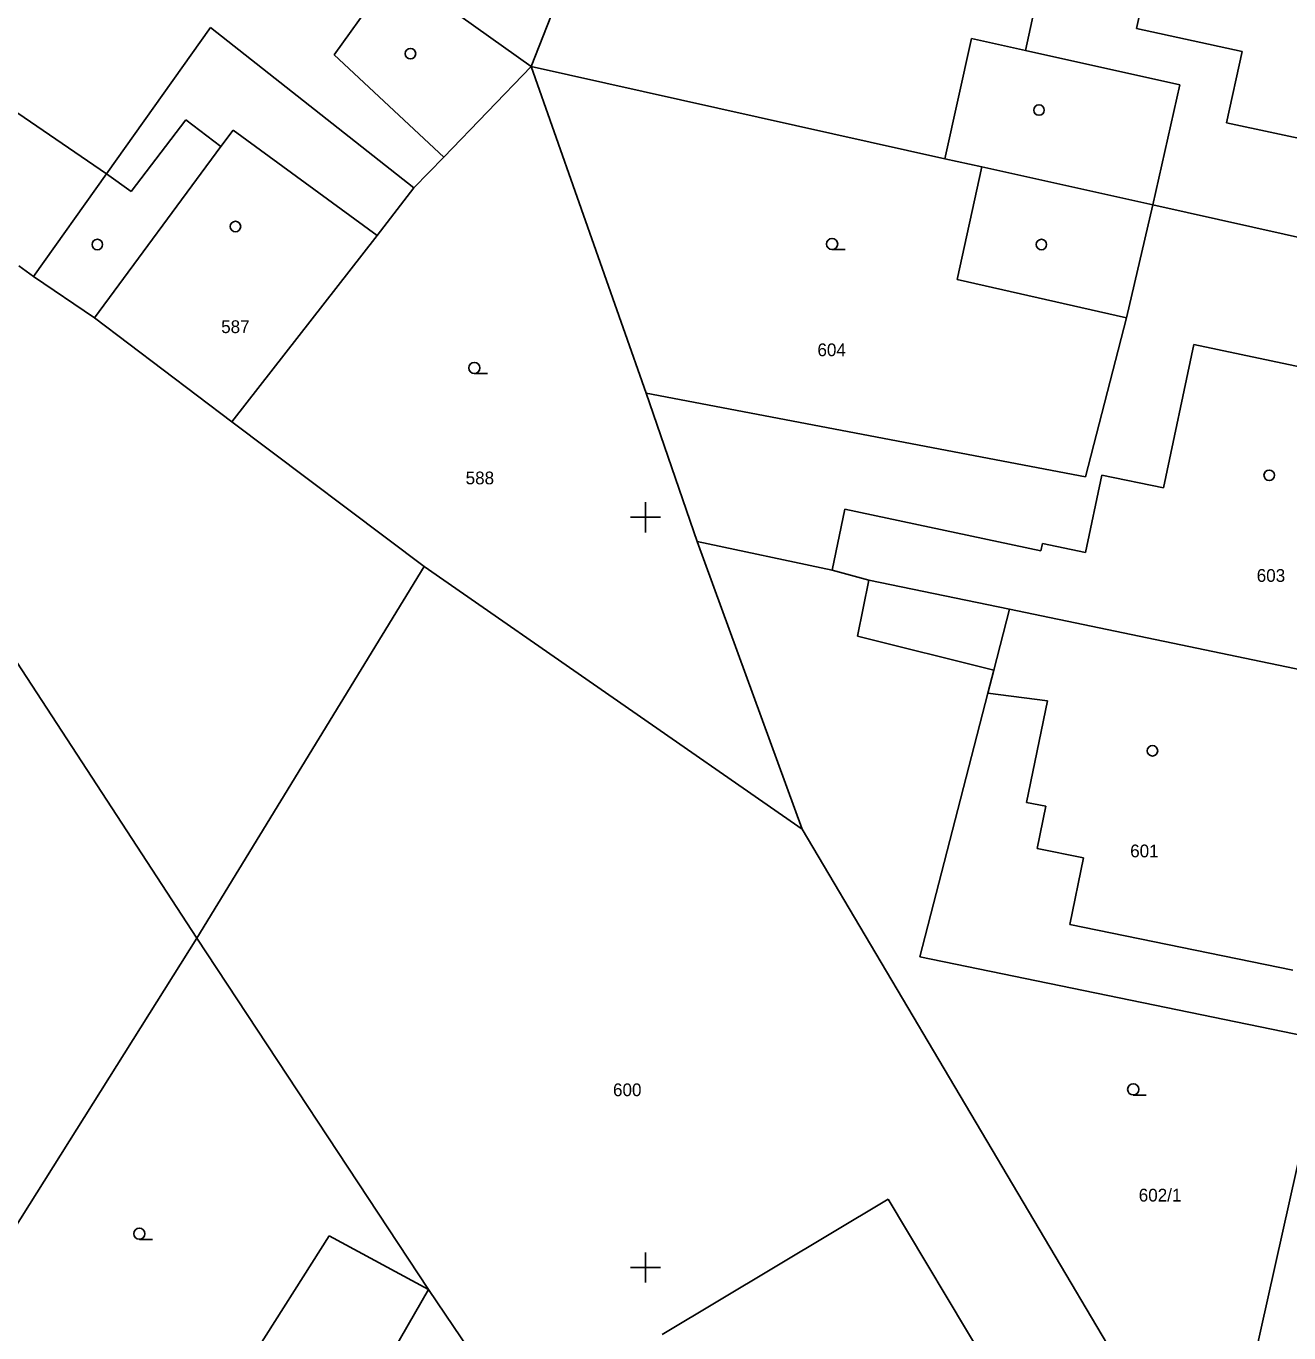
# Model space of a CAD drawing. Extents: x -702257 to -701487, y -1009871 to -1008841.
# Drawn here: x -701770.63 to -701728.56, y -1009477.18 to -1009433.63 of the extents above; entities that cross this region are included whole.
import ezdxf

# ---------------------------------------------------------------- set-up
doc = ezdxf.new("R2010")
doc.units = 0
for name, color, linetype in [('Z_hektometricka_sit', 7, 'Continuous'), ('Z_katastr_cisla_pozemkova', 7, 'Continuous'), ('Z_katastr_cisla_stavebni', 7, 'Continuous'), ('Z_katastr_hranice', 7, 'Continuous'), ('Z_katastr_vnitrni_kresba', 7, 'Continuous'), ('Z_katastr_znacky_budov', 7, 'Continuous'), ('Z_katastr_znacky_kultur', 7, 'Continuous')]:
    doc.layers.add(name, color=color, linetype=linetype)

msp = doc.modelspace()

# ---------------------------------------------------------------- linework, layer by layer
at = {"layer": 'Z_hektometricka_sit'}
for p, q in [((-701750, -1009449.5), (-701750, -1009450.5)), ((-701750, -1009449.5), (-701750, -1009450.5)), ((-701750.5, -1009450), (-701749.5, -1009450)), ((-701750.5, -1009450), (-701749.5, -1009450)), ((-701750, -1009474.5), (-701750, -1009475.5)), ((-701750, -1009474.5), (-701750, -1009475.5)), ((-701750.5, -1009475), (-701749.5, -1009475)), ((-701750.5, -1009475), (-701749.5, -1009475))]:
    msp.add_line(p, q, dxfattribs=at)
at = {"layer": 'Z_katastr_hranice'}
for p, q in [((-701736.23, -1009429.41), (-701737.34, -1009434.44)), ((-701758.33, -1009431.75), (-701753.81, -1009434.98)), ((-701753.81, -1009434.98), (-701753, -1009432.94)), ((-701767.95, -1009438.55), (-701764.49, -1009433.68)), ((-701764.49, -1009433.68), (-701757.71, -1009439.02)), ((-701739.13, -1009434.04), (-701740.02, -1009438.05)), ((-701737.34, -1009434.44), (-701739.13, -1009434.04)), ((-701756.72, -1009438), (-701753.81, -1009434.98)), ((-701749.97, -1009445.86), (-701753.81, -1009434.98)), ((-701740.02, -1009438.05), (-701753.81, -1009434.98)), ((-701757.71, -1009439.02), (-701756.72, -1009438)), ((-701738.79, -1009438.32), (-701740.02, -1009438.05)), ((-701770.39, -1009441.98), (-701767.95, -1009438.55)), ((-701738.79, -1009438.32), (-701739.61, -1009442.07)), ((-701733.09, -1009439.59), (-701738.79, -1009438.32)), ((-701758.94, -1009440.61), (-701757.71, -1009439.02)), ((-701721.46, -1009442.19), (-701733.09, -1009439.59)), ((-701763.78, -1009446.82), (-701758.94, -1009440.61)), ((-701770.87, -1009441.62), (-701770.39, -1009441.98)), ((-701770.39, -1009441.98), (-701768.35, -1009443.35)), ((-701739.61, -1009442.07), (-701733.97, -1009443.35)), ((-701768.35, -1009443.35), (-701763.78, -1009446.82)), ((-701733.97, -1009443.35), (-701735.34, -1009448.65)), ((-701748.28, -1009450.81), (-701749.97, -1009445.86)), ((-701735.34, -1009448.65), (-701749.97, -1009445.86)), ((-701763.78, -1009446.82), (-701757.37, -1009451.64)), ((-701744.78, -1009460.39), (-701748.28, -1009450.81)), ((-701748.28, -1009450.81), (-701743.78, -1009451.76)), ((-701764.94, -1009464.02), (-701757.37, -1009451.64)), ((-701757.37, -1009451.64), (-701744.78, -1009460.39)), ((-701743.78, -1009451.76), (-701742.55, -1009452.09)), ((-701742.55, -1009452.09), (-701742.93, -1009453.96)), ((-701737.87, -1009453.06), (-701742.55, -1009452.09)), ((-701772.57, -1009452.34), (-701764.94, -1009464.02)), ((-701726.45, -1009455.44), (-701737.87, -1009453.06)), ((-701742.93, -1009453.96), (-701738.39, -1009455.09)), ((-701738.39, -1009455.09), (-701738.59, -1009455.86)), ((-701738.59, -1009455.86), (-701740.86, -1009464.65)), ((-701733.55, -1009479.33), (-701744.78, -1009460.39)), ((-701772.93, -1009476.73), (-701764.94, -1009464.02)), ((-701757.23, -1009475.73), (-701764.94, -1009464.02)), ((-701740.86, -1009464.65), (-701727.35, -1009467.43)), ((-701727.35, -1009467.43), (-701730.45, -1009481.35)), ((-701741.91, -1009472.72), (-701749.44, -1009477.23)), ((-701735.86, -1009482.82), (-701741.91, -1009472.72)), ((-701760.54, -1009473.94), (-701763.28, -1009478.26)), ((-701757.23, -1009475.73), (-701760.54, -1009473.94)), ((-701759.94, -1009480.44), (-701757.23, -1009475.73)), ((-701751.57, -1009484.07), (-701757.23, -1009475.73))]:
    msp.add_line(p, q, dxfattribs=at)
at = {"layer": 'Z_katastr_vnitrni_kresba'}
for p, q in [((-701733.64, -1009433.71), (-701732.86, -1009430.16)), ((-701760.37, -1009434.59), (-701758.33, -1009431.75)), ((-701730.12, -1009434.48), (-701733.64, -1009433.71)), ((-701756.72, -1009438), (-701760.37, -1009434.59)), ((-701737.34, -1009434.44), (-701732.2, -1009435.59)), ((-701730.64, -1009436.85), (-701730.12, -1009434.48)), ((-701732.2, -1009435.59), (-701733.09, -1009439.59)), ((-701767.95, -1009438.55), (-701771.55, -1009436.1)), ((-701765.31, -1009436.75), (-701767.13, -1009439.14)), ((-701764.14, -1009437.64), (-701765.31, -1009436.75)), ((-701722.5, -1009438.59), (-701730.64, -1009436.85)), ((-701763.73, -1009437.1), (-701764.14, -1009437.64)), ((-701758.94, -1009440.61), (-701763.73, -1009437.1)), ((-701764.14, -1009437.64), (-701768.35, -1009443.35)), ((-701767.13, -1009439.14), (-701767.95, -1009438.55)), ((-701733.09, -1009439.59), (-701733.97, -1009443.35)), ((-701731.73, -1009444.24), (-701732.74, -1009449.02)), ((-701724.4, -1009445.8), (-701731.73, -1009444.24)), ((-701734.79, -1009448.59), (-701735.34, -1009451.17)), ((-701732.74, -1009449.02), (-701734.79, -1009448.59)), ((-701743.35, -1009449.73), (-701743.78, -1009451.76)), ((-701736.82, -1009451.12), (-701743.35, -1009449.73)), ((-701736.77, -1009450.87), (-701736.82, -1009451.12)), ((-701735.34, -1009451.17), (-701736.77, -1009450.87)), ((-701737.87, -1009453.06), (-701738.39, -1009455.09)), ((-701736.6, -1009456.11), (-701738.59, -1009455.86)), ((-701737.3, -1009459.5), (-701736.6, -1009456.11)), ((-701736.66, -1009459.63), (-701737.3, -1009459.5)), ((-701736.95, -1009461.04), (-701736.66, -1009459.63)), ((-701735.4, -1009461.35), (-701736.95, -1009461.04)), ((-701735.86, -1009463.57), (-701735.4, -1009461.35)), ((-701728.43, -1009465.09), (-701735.86, -1009463.57))]:
    msp.add_line(p, q, dxfattribs=at)
at = {"layer": 'Z_katastr_znacky_budov'}
for centre in [(-701757.827, -1009434.549), (-701736.887, -1009436.429), (-701763.657, -1009440.309), (-701768.257, -1009440.909), (-701736.807, -1009440.909), (-701729.217, -1009448.599), (-701733.107, -1009457.779)]:
    msp.add_circle(centre, 0.175, dxfattribs=at)
at = {"layer": 'Z_katastr_znacky_kultur'}
for p, q in [((-701743.778, -1009441.08), (-701743.341, -1009441.08)), ((-701755.698, -1009445.21), (-701755.261, -1009445.21)), ((-701733.748, -1009469.25), (-701733.311, -1009469.25)), ((-701766.858, -1009474.06), (-701766.421, -1009474.06))]:
    msp.add_line(p, q, dxfattribs=at)
for centre in [(-701743.778, -1009440.892), (-701755.698, -1009445.022), (-701733.748, -1009469.062), (-701766.858, -1009473.872)]:
    msp.add_circle(centre, 0.187, dxfattribs=at)

# ---------------------------------------------------------------- texts
at = {"layer": 'Z_katastr_cisla_pozemkova'}
for s, p in [('604', (-701744.268, -1009444.63)), ('588', (-701755.988, -1009448.9)), ('600', (-701751.078, -1009469.289)), ('602/1', (-701733.564, -1009472.799))]:
    msp.add_text(s, height=0.425, dxfattribs=at).set_placement(p)
at = {"layer": 'Z_katastr_cisla_stavebni'}
for s, p in [('587', (-701764.133, -1009443.86)), ('603', (-701729.633, -1009452.15)), ('601', (-701733.849, -1009461.33))]:
    msp.add_text(s, height=0.425, dxfattribs=at).set_placement(p)

doc.saveas('drawing.dxf')
